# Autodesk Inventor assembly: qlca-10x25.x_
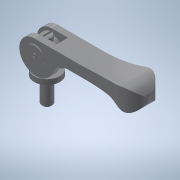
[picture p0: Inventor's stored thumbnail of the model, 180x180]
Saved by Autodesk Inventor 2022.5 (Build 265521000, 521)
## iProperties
Part Number: qlca-10x25.x_
Material: 一般
Document SubType Name: Assembly
Designer: ImaoCorp
Sending System: SOLIDWORKS 2017-2017317
MC: AMD64
MC_MODEL: Intel64 Family 6 Model 60 Stepping 3, GenuineIntel
OS: Windows_NT
FRU: Parasolid Version 29.0, build 201,  4-17-2017
FORMAT: text
GUISE: transmit
KEY: qlca-10x25
FILE: qlca-10x25.x_t
DATE: Wed Sep 04 15:47:14 2019
Author: ImaoCorp
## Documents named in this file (4)
- X:\14_SW2022-Inv2022\00_全2023-1023新製品(TCC)まで\q\qlca-10x25\QLCA-10X25.iam
- X:\14_SW2022-Inv2022\00_全2023-1023新製品(TCC)まで\q\qlca-10x25\qlca-10x25_01.ipt
- X:\14_SW2022-Inv2022\00_全2023-1023新製品(TCC)まで\q\qlca-10x25\qlca-10x25_02.ipt
- X:\14_SW2022-Inv2022\00_全2023-1023新製品(TCC)まで\q\qlca-10x25\qlca-10x25_03.ipt
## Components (3 placed, 3 different names)
1. qlca-10x25_01
2. qlca-10x25_02
3. qlca-10x25_03
